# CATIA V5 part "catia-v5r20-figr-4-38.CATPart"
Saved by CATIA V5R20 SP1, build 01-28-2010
Part number: Part1
Bounding box of the stored display mesh (mm): x -89.975 to 89.975, y -89.975 to 89.975, z 0 to 190
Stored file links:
  D:\v5_r20\psrt_files_downloaded\c04catia-v5r20-prt\catia-v5r20-figr-4-38.CATPart
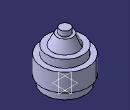
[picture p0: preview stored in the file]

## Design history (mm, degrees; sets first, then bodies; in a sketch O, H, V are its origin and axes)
Set1
  Line1 "Y Axis": stored without definition
  Line2 "Y Axis": stored without definition
  Line3 "X Axis": stored without definition
  Line4 "Z Axis": stored without definition
Body1 (main body)
  Sketch1 on yz-plane, origin (0, 0, 0), H (0, 1, 0), V (0, 0, 1)
    line L1 (0, 0) -> (80, 0)
    line L2 (80, 0) -> (80, 30)
    line L3 (80, 30) -> (90, 30)
    line L4 (90, 30) -> (90, 100)
    line L5 (90, 100) -> (70, 100)
    line L6 (70, 100) -> (70, 130)
    line L7 (70, 130) -> (50, 130)
    line L8 (50, 130) -> (30, 170)
    line L9 (30, 170) -> (20, 170)
    line L10 (20, 170) -> (20, 190)
    line L11 (20, 190) -> (0, 190)
    point P11 (0, 190)
    line L12 (0, 190) -> (0, 0)
    axis line L13 (0, -40) -> (0, 230)
    point P12 (0, -40)
    point P13 (0, 230)
    horizontal: L1 H, L3 H, L5 H, L7 H, L9 H, L11 H
    vertical: L2 V, L4 V, L6 V, L10 V, L12 V, L13 V
    coincidence: P11 V, P12 V, P13 L8
  Shaft1: profile Sketch1, axis Sketch1.L13, angle 360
